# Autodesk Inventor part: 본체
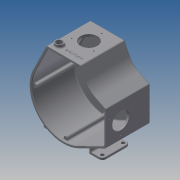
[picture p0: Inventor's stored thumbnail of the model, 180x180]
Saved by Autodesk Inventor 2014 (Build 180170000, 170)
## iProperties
Created: 2017-05
Part Number: 본체
Material: 알루미늄 6061
Document SubType Name: Modeling
Designer: mduedu
Density: 2.71 g/cm^3
Mass: 1300.76 g
Surface Area: 1825.93 cm^2
Volume: 479.986 cm^3
Appearance: 기본값
Author: mduedu
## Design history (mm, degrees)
sketch "스케치1"
  geometry: L1 (-71.801, 35.28)-(-40, 100); L2 (-40, 100)-(40, 100); L3 (40, 100)-(59.768, 59.768); L4 (59.768, 59.768)-(100, 40); L5 (100, 40)-(100, -40); L6 (100, -40)-(35.28, -71.801); A1 r 80 centre (0, 0) between (-71.801, 35.28) and (35.28, -71.801); 3 further points
  constraints: 12 end point, 4 tangent, 2 midpoint, 2 point on circle, 1 centre point, 1 coincident, 1 horizontal, 1 horizontal alignment, 1 perpendicular, 1 vertical alignment
  dimensions: "d0" = 160 diameter of A1; "d2" = 100 distance from line of L2 point (0, 0); "d3" = 100 distance from line of L5 point (0, 0); "d4" = 80 distance of L1.end L2.end; "d5" = 80 distance of L4.end L5.end
extrude "돌출1" new body sketch "스케치1" distance "d6" = 5; taper "d7" = 0 deg
fillet "모깎기1" dims "d8" = 50
sketch "스케치2"
  geometry: C1 r 22 at (0, 0); 1 further point
  constraints: 1 centre point, 1 coincident
  dimensions: "d9" = 44 diameter of C1
extrude "돌출2" join sketch "스케치2" distance "d10" = 22.5; taper "d11" = 0 deg
sketch "스케치3"
  geometry: C1 r 18.5 at (0, 0); 1 further point
  constraints: 1 centre point, 1 coincident
  dimensions: "d12" = 37 diameter of C1
extrude "돌출3" cut sketch "스케치3" distance "d13" = 9; taper "d14" = 0 deg
fillet "모깎기2" dims "d15" = 3
sketch "스케치4"
  geometry: L1 (35.28, -71.801)-(100, -40) reference; L2 (100, -40)-(100, 40) reference; L3 (100, 40)-(75.073, 52.248) reference; L4 (52.248, 75.073)-(40, 100) reference; L5 (40, 100)-(-40, 100) reference; L6 (-40, 100)-(-71.801, 35.28) reference; L7 (-36.886, 95)-(36.886, 95); L8 (36.886, 95)-(47.76, 72.868); L9 (72.868, 47.76)-(95, 36.886); L10 (95, 36.886)-(95, -36.886); L11 (95, -36.886)-(33.075, -67.313); L12 (-67.313, 33.075)-(-36.886, 95); C1 r 25 at (0, 0) reference; A1 r 50 centre (97.123, 97.123) between (52.248, 75.073) and (75.073, 52.248) reference; A2 r 80 centre (0, 0) between (-71.801, 35.28) and (35.28, -71.801) reference; A3 r 55 centre (97.123, 97.123) between (47.76, 72.868) and (72.868, 47.76); A4 r 75 centre (0, 0) between (-67.313, 33.075) and (33.075, -67.313); 1 further point
  constraints: 12 end point, 4 point on circle, 2 centre point, 7 other
  dimensions: "d16" = 5 distance between parallel lines of L7 L5
extrude "돌출4" join sketch "스케치4" distance "d17" = 100; taper "d18" = 0 deg
sketch "스케치5"
  geometry: L1 (80, 0)-(0, 0) reference; C1 r 20 at (40, -45); 2 further points
  constraints: 1 centre point, 1 midpoint, 1 vertical alignment
  dimensions: "d19" = 40 diameter of C1; "d21" = 45 distance from line of C1.centre L1
extrude "돌출5" cut sketch "스케치5" stored distance "d22" = 100; taper "d23" = 0 deg
sketch "스케치6"
  geometry: L1 (0, 0)-(0, -105) reference; L2 (80, -105)-(0, -105) reference; C1 r 9 at (14, -89); 1 further point
  constraints: 1 centre point
  dimensions: "d24" = 18 diameter of C1; "d26" = 14 distance from line of C1.centre L1; "d27" = 16 distance from line of C1.centre L2
extrude "돌출6" join sketch "스케치6" distance "d28" = 7; taper "d29" = 0 deg
hole "구멍1" diameter "d32" = 14; stored, may be unused: countersink angle "d36" = 90 deg, drill point angle "d38" = 118 deg; dims "d33" = 6, "d34" = 4, "d35" = 2, "d37" = 8, "d39" = 10, "d40" = 10
sketch "스케치7"
  geometry: L1 (-105, 0)-(-105, 80) reference; L2 (0, 0)-(0, 80) reference; C1 r 20 at (-70, 40); 2 further points
  constraints: 1 centre point, 1 horizontal alignment, 1 midpoint
  dimensions: "d41" = 40 diameter of C1; "d42" = 35 distance from line of C1.centre L1
extrude "돌출7" cut sketch "스케치7" stored distance "d43" = 7; taper "d44" = 0 deg
node "작업 평면1"
sketch "스케치8"
  geometry: L1 (47.76, 72.868)-(36.886, 95) reference; L2 (36.886, 95)-(-36.886, 95) reference; L3 (-36.886, 95)-(-67.313, 33.075) reference; L4 (33.075, -67.313)-(95, -36.886) reference; L5 (95, -36.886)-(95, 36.886) reference; L6 (95, 36.886)-(72.868, 47.76) reference; L7 (95, 36.886)-(95, -36.886) reference; L8 (-36.886, 95)-(36.886, 95) reference; L9 (36.886, 95)-(47.76, 72.868) reference; L10 (-71, 4)-(-74.893, 4); L11 (-71, -4)-(-74.893, -4); L12 (-4, -71)-(-4, -74.893); L13 (4, -71)-(4, -74.893); L14 (30.394, 91)-(30.394, 95); L15 (34.394, 87)-(40.817, 87); L16 (30.394, 95)-(36.886, 95); L17 (36.886, 95)-(37.984, 92.764); L18 (91, 30.394)-(95, 30.394); L19 (87, 34.394)-(87, 40.817); L20 (87, 40.817)-(95, 36.886); L21 (95, 36.886)-(95, 30.394); C1 r 25 at (0, 0) reference; A1 r 75 centre (0, 0) between (-67.313, 33.075) and (33.075, -67.313) reference; A2 r 55 centre (97.123, 97.123) between (47.76, 72.868) and (72.868, 47.76) reference; A3 r 4 centre (-71, 0) between (-71, 4) and (-71, -4); A4 r 4 centre (0, -71) between (-4, -71) and (4, -71); A5 r 4 centre (34.394, 91) between (30.394, 91) and (34.394, 87); A6 r 75 centre (0, 0) between (-67.313, 33.075) and (33.075, -67.313) reference; A7 r 4 centre (91, 34.394) between (91, 30.394) and (87, 34.394); 1 further point
  constraints: 24 end point, 17 point on circle, 14 tangent, 5 point on line, 4 centre point, 3 equal radius, 3 perpendicular, 3 vertical, 2 collinear, 2 horizontal, 1 horizontal alignment, 1 parallel, 1 vertical alignment
  dimensions: "d46" = 8 diameter of A3
extrude "돌출8" join sketch "스케치8" stored distance "d49" = 7; taper "d50" = 0 deg
node "작업 평면2"
sketch "스케치9"
  geometry: L1 (71.801, 0)-(71.801, 105) reference; L2 (71.801, 0)-(-35.28, 0) reference; L3 (-35.28, 0)-(-35.28, 105) reference; L4 (71.801, 105)-(-35.28, 105) reference; L5 (40, 0)-(40, 105) reference; L6 (71.801, 52.5)-(-35.28, 52.5); L7 (71.801, 20)-(40, 20); L8 (40, 20)-(40, 85); L9 (40, 85)-(71.801, 85); L10 (71.801, 85)-(71.801, 20); 1 further point
  constraints: 10 end point, 2 midpoint, 2 parallel, 2 point on line, 1 horizontal, 1 perpendicular, 1 other
  dimensions: "d52" = 20 distance between parallel lines of L7 L2
extrude "돌출9" join sketch "스케치9" distance "d53" = 5; taper "d54" = 0 deg
fillet "모깎기3" dims "d55" = 8
sketch "스케치10"
  geometry: C1 r 4 at (-63.801, -28); C2 r 4 at (-63.801, -77); A1 r 8 centre (-63.801, -28) between (-63.801, -20) and (-71.801, -28) reference; A2 r 8 centre (-63.801, -77) between (-71.801, -77) and (-63.801, -85) reference; 1 further point
  constraints: 2 centre point, 2 coincident, 1 equal radius
  dimensions: "d56" = 8 diameter of C1
extrude "돌출10" cut sketch "스케치10" stored distance "d57" = 50.5; taper "d58" = 0 deg
sketch "스케치11"
  geometry: L1 (-63.801, -20)-(-40, -20) reference; L2 (-40, -20)-(-40, -85) reference; L3 (-40, -85)-(-63.801, -85) reference; L4 (-71.801, -77)-(-71.801, -28) reference; L5 (71.801, -77)-(71.801, -28) reference; L6 (40, -85)-(63.801, -85) reference; L7 (40, -20)-(40, -85) reference; L8 (63.801, -20)-(40, -20) reference; L9 (-40, -85)-(-45, -85); L10 (-45, -85)-(-45, -20); L11 (-45, -20)-(-40, -20); L12 (-40, -20)-(-40, -85); L13 (40, -85)-(45, -85); L14 (45, -85)-(45, -20); L15 (45, -20)-(40, -20); L16 (40, -20)-(40, -85); C1 r 4 at (-63.801, -28) reference; C2 r 4 at (-63.801, -77) reference; C3 r 4 at (63.801, -28) reference; C4 r 4 at (63.801, -77) reference; A1 r 8 centre (-63.801, -28) between (-63.801, -20) and (-71.801, -28) reference; A2 r 8 centre (-63.801, -77) between (-71.801, -77) and (-63.801, -85) reference; A3 r 8 centre (63.801, -28) between (71.801, -28) and (63.801, -20) reference; A4 r 8 centre (63.801, -77) between (63.801, -85) and (71.801, -77) reference; 1 further point
  constraints: 16 end point, 4 parallel, 2 horizontal, 2 perpendicular, 2 point on line
  dimensions: "d59" = 5 distance of L10.end L11.end; "d61" = 5 distance of L14.end L15.end
extrude "돌출11" join sketch "스케치11" stored distance "d62" = 5; taper "d63" = 0 deg
fillet "모깎기4" dims "d64" = 3
fillet "모깎기5" dims "d65" = 1
fillet "모깎기6" dims "d66" = 1
fillet "모깎기8" dims "d68" = 1
fillet "모깎기9" dims "d70" = 3, "d101" = 1
fillet "모깎기10" dims "d71" = 3
fillet "모깎기11" dims "d72" = 3
fillet "모깎기12" dims "d73" = 3
fillet "모깎기13" dims "d76" = 3
chamfer "모따기1" distance "d77" = 0.5; stored, may be unused: second distance "d78" = 2, angle "d79" = 45 deg
sketch "스케치13"
  geometry: L1 (76.263, 0)-(0, 0) reference; 2 further points
  constraints: 1 other
  dimensions: "d83" = 15 distance from line of point (48.131, 15) L1; "d84" = 10 horizontal distance of point (48.131, 15) point (38.131, 105)
feature "엠보싱1" sketch "스케치13" dims "d0" = 160, "d2" = 100, "d3" = 100, "d4" = 80, "d5" = 80, "d85" = 0.5, "d86" = 0
chamfer "모따기2" distance "d87" = 1; stored, may be unused: second distance "d88" = 2, angle "d89" = 45 deg
chamfer "모따기3" distance "d90" = 1; stored, may be unused: second distance "d91" = 2, angle "d92" = 45 deg
sketch "스케치14"
  geometry: 3 further points
  constraints: 3 other
hole "구멍2" sketch "스케치14" at (-55.375, -40), (-3.414, -40), (-29.394, -85) diameter "d93" = 2.459; stored, may be unused: countersink angle "d97" = 90 deg, drill point angle "d99" = 0 deg; dims "d94" = 6, "d95" = 4, "d96" = 2, "d98" = 8
sketch "스케치15"
  geometry: 3 further points
  constraints: 3 other
hole "구멍4" sketch "스케치15" at (-55.981, -14.394), (-4.019, -14.394), (-30, -59.394) diameter "d102" = 2.459; stored, may be unused: countersink angle "d106" = 90 deg, drill point angle "d108" = 0 deg; dims "d103" = 6, "d104" = 4, "d105" = 2, "d107" = 8
sketch "스케치16"
  geometry: 4 further points
  constraints: 4 other
hole "구멍6" sketch "스케치16" at (0, -71), (91, 34.394), (34.394, 91), (-71, 0) diameter "d109" = 2.459; stored, may be unused: countersink angle "d113" = 90 deg, drill point angle "d115" = 120 deg; dims "d110" = 8.5, "d111" = 4, "d112" = 2, "d114" = 10
node "솔리드1"
mirror "대칭1"
node "투영된 루프1"
node "투영된 루프2"
node "투영된 루프3"
node "투영된 루프4"
node "투영된 루프5"
other parameters: "d45" = 95
